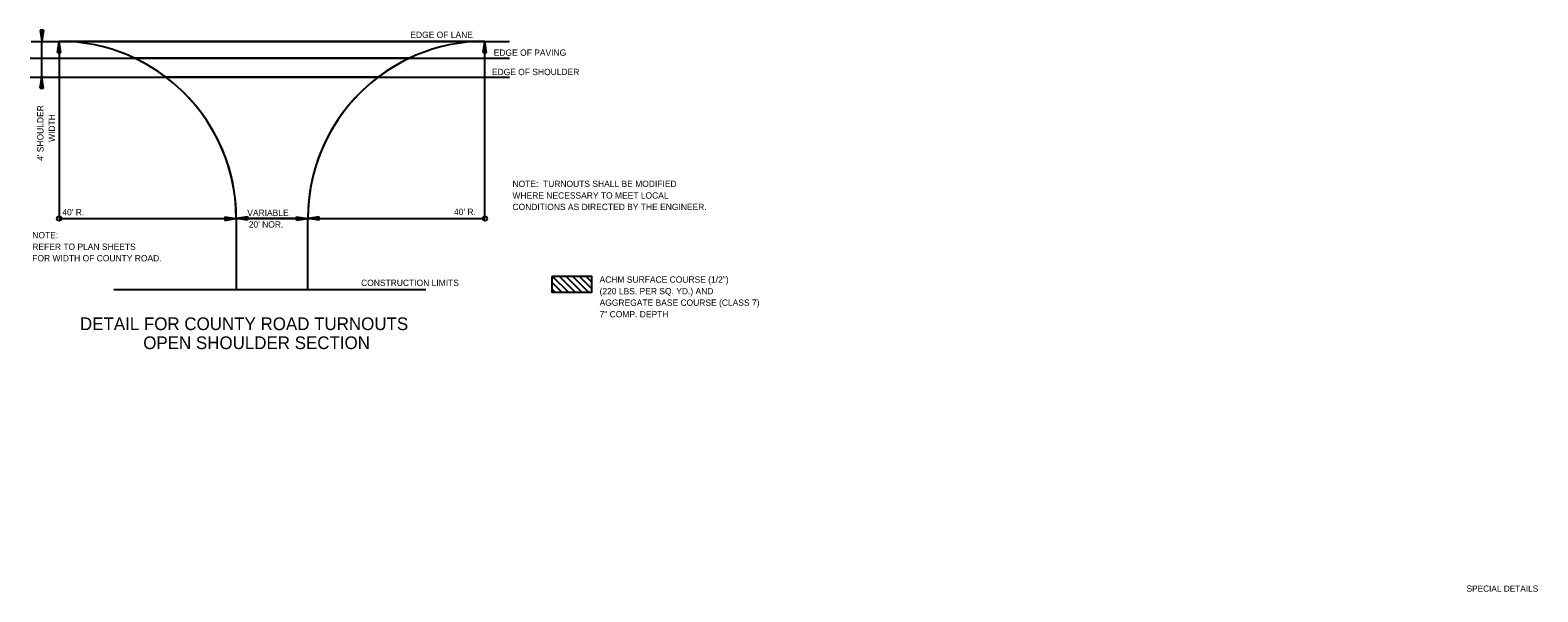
# Model space of a CAD drawing. Extents: x 836 to 5683, y -463 to 1545.
# Drawn here: x 2060 to 3490, y 1013 to 1545 of the extents above; entities that cross this region are included whole.
import ezdxf

# ---------------------------------------------------------------- set-up
doc = ezdxf.new("R2010")
doc.units = 0
doc.layers.add('Default', color=7, linetype='Continuous')
doc.layers.add('R_Border Prem', color=7, linetype='Continuous')

msp = doc.modelspace()

# ---------------------------------------------------------------- linework, layer by layer
at = {"layer": 'Default'}
for p, q in [((2069.7, 1544.8), (2071.2, 1534.2)), ((2072.8, 1544.8), (2069.7, 1544.8)), ((2069.9, 1544.8), (2071.2, 1536)), ((2070.2, 1544.8), (2071.2, 1537.8)), ((2070.5, 1544.8), (2071.2, 1539.5)), ((2070.7, 1544.8), (2071.2, 1541.4)), ((2071, 1544.8), (2071.2, 1543.1)), ((2072.8, 1544.8), (2071.2, 1534.2)), ((2071.8, 1544.8), (2071.2, 1541.4)), ((2072.3, 1544.8), (2071.2, 1537.8)), ((2072.6, 1544.8), (2071.2, 1536)), ((2072, 1544.8), (2071.2, 1539.5)), ((2071.5, 1544.8), (2071.2, 1543.1)), ((2061.2, 1534.2), (2514.7, 1534.2)), ((2071.2, 1500.3), (2071.2, 1534.2)), ((2086.2, 1523.6), (2087.8, 1534.2)), ((2086.5, 1523.6), (2087.8, 1532.4)), ((2086.7, 1523.6), (2087.8, 1530.6)), ((2089.4, 1523.6), (2087.8, 1534.2)), ((2087.8, 1534.2), (2087.8, 1366.3)), ((2491.4, 1534.2), (2087.8, 1534.2)), ((2089.1, 1523.6), (2087.8, 1532.4)), ((2088.9, 1523.6), (2087.8, 1530.6)), ((2251.1, 1533.8), (2251.3, 1534.3)), ((2251.3, 1534.2), (2251.1, 1533.8)), ((2251.1, 1533.8), (2251.3, 1534)), ((2489.8, 1523.6), (2491.4, 1534.2)), ((2490.1, 1523.6), (2491.4, 1532.4)), ((2490.3, 1523.6), (2491.4, 1530.6)), ((2493, 1523.6), (2491.4, 1534.2)), ((2491.4, 1366.3), (2491.4, 1534.2)), ((2492.7, 1523.6), (2491.4, 1532.4)), ((2492.4, 1523.6), (2491.4, 1530.6)), ((2060.3, 1518.3), (2514.7, 1518.3)), ((2086.2, 1523.6), (2089.4, 1523.6)), ((2087, 1523.6), (2087.8, 1528.8)), ((2087.3, 1523.6), (2087.8, 1527.1)), ((2087.5, 1523.6), (2087.8, 1525.3)), ((2088.6, 1523.6), (2087.8, 1528.8)), ((2088.3, 1523.6), (2087.8, 1527.1)), ((2088.1, 1523.6), (2087.8, 1525.3)), ((2420.1, 1518.3), (2159.1, 1518.3)), ((2489.8, 1523.6), (2493, 1523.6)), ((2490.6, 1523.6), (2491.4, 1528.8)), ((2490.9, 1523.6), (2491.4, 1527)), ((2491.1, 1523.6), (2491.4, 1525.3)), ((2492.2, 1523.6), (2491.4, 1528.8)), ((2491.9, 1523.6), (2491.4, 1527)), ((2491.7, 1523.6), (2491.4, 1525.3)), ((2060.3, 1500.3), (2514.7, 1500.3)), ((2069.7, 1489.7), (2071.2, 1500.3)), ((2069.7, 1489.7), (2072.8, 1489.7)), ((2069.9, 1489.7), (2071.2, 1498.5)), ((2070.2, 1489.7), (2071.2, 1496.7)), ((2070.5, 1489.7), (2071.2, 1494.9)), ((2070.8, 1489.7), (2071.2, 1493.1)), ((2071, 1489.7), (2071.2, 1491.4)), ((2072.8, 1489.7), (2071.2, 1500.3)), ((2072.6, 1489.7), (2071.2, 1498.5)), ((2072.3, 1489.7), (2071.2, 1496.7)), ((2072, 1489.7), (2071.2, 1494.9)), ((2071.8, 1489.7), (2071.2, 1493.1)), ((2071.5, 1489.7), (2071.2, 1491.4)), ((2390.2, 1500.3), (2188.9, 1500.3)), ((2087.8, 1366.3), (2255.7, 1366.3)), ((2244.7, 1367.8), (2255.3, 1366.2)), ((2244.7, 1367.8), (2244.7, 1364.6)), ((2244.7, 1367.6), (2253.5, 1366.2)), ((2244.7, 1367.3), (2251.7, 1366.2)), ((2244.7, 1367), (2249.9, 1366.2)), ((2244.7, 1366.7), (2248.1, 1366.2)), ((2244.7, 1366.5), (2246.4, 1366.2)), ((2244.7, 1364.6), (2255.3, 1366.2)), ((2244.7, 1365.7), (2248.1, 1366.2)), ((2244.7, 1365.2), (2251.7, 1366.2)), ((2244.7, 1364.9), (2253.5, 1366.2)), ((2244.7, 1365.4), (2249.9, 1366.2)), ((2244.7, 1366), (2246.4, 1366.2)), ((2255.7, 1366.3), (2255.7, 1299)), ((2255.7, 1366.3), (2323.5, 1366.3)), ((2255.7, 1366.3), (2323.5, 1366.3)), ((2255.7, 1366.3), (2256.9, 1366.3)), ((2256.9, 1366.3), (2255.7, 1366.3)), ((2255.7, 1366.3), (2255.7, 1299)), ((2266.4, 1368), (2255.8, 1366.5)), ((2255.8, 1366.5), (2266.4, 1368)), ((2266.4, 1364.9), (2255.8, 1366.5)), ((2256.9, 1366.3), (2255.8, 1366.5)), ((2266.4, 1364.9), (2256.9, 1366.3)), ((2266.4, 1367.8), (2257.6, 1366.5)), ((2266.4, 1365.1), (2257.6, 1366.5)), ((2266.4, 1367.5), (2259.4, 1366.5)), ((2266.4, 1365.4), (2259.4, 1366.5)), ((2266.4, 1367.3), (2261.2, 1366.5)), ((2266.4, 1365.7), (2261.2, 1366.5)), ((2266.4, 1367), (2263, 1366.5)), ((2266.4, 1365.9), (2263, 1366.5)), ((2266.4, 1366.7), (2264.8, 1366.5)), ((2266.4, 1366.2), (2264.8, 1366.5)), ((2266.4, 1368.1), (2266.4, 1366.3)), ((2266.4, 1364.9), (2266.4, 1368)), ((2266.4, 1366.3), (2312.9, 1366.3)), ((2312.9, 1366.3), (2266.4, 1366.3)), ((2266.4, 1366.3), (2266.4, 1364.9)), ((2312.9, 1367.9), (2323.5, 1366.3)), ((2312.9, 1367.9), (2312.9, 1364.7)), ((2312.9, 1366.3), (2312.9, 1367.9)), ((2312.9, 1367.9), (2323.5, 1366.3)), ((2312.9, 1367.6), (2321.7, 1366.3)), ((2312.9, 1367.3), (2319.9, 1366.3)), ((2312.9, 1367), (2318.1, 1366.3)), ((2312.9, 1366.8), (2316.3, 1366.3)), ((2312.9, 1366.5), (2314.6, 1366.3)), ((2312.9, 1364.7), (2323.5, 1366.3)), ((2312.9, 1365.8), (2316.3, 1366.3)), ((2312.9, 1365.2), (2319.9, 1366.3)), ((2312.9, 1364.9), (2321.7, 1366.3)), ((2312.9, 1365.5), (2318.1, 1366.3)), ((2312.9, 1366), (2314.6, 1366.3)), ((2323.5, 1366.3), (2312.9, 1364.7)), ((2312.9, 1364.7), (2312.9, 1366.3)), ((2323.5, 1299), (2323.5, 1366.3)), ((2323.5, 1366.3), (2491.4, 1366.3)), ((2323.5, 1299), (2323.5, 1366.3)), ((2334.2, 1368), (2323.7, 1366.5)), ((2334.2, 1364.9), (2323.7, 1366.5)), ((2334.2, 1367.8), (2325.4, 1366.5)), ((2334.2, 1365.1), (2325.4, 1366.5)), ((2334.2, 1367.5), (2327.2, 1366.5)), ((2334.2, 1365.4), (2327.2, 1366.5)), ((2334.2, 1367.3), (2329, 1366.5)), ((2334.2, 1365.7), (2329, 1366.5)), ((2334.2, 1367), (2330.8, 1366.5)), ((2334.2, 1365.9), (2330.8, 1366.5)), ((2334.2, 1366.7), (2332.5, 1366.5)), ((2334.2, 1366.2), (2332.5, 1366.5)), ((2334.2, 1364.9), (2334.2, 1368)), ((2139.7, 1299), (2435.3, 1299)), ((2255.7, 1299), (2323.5, 1299))]:
    msp.add_line(p, q, dxfattribs=at)
for points in [[(2188.9, 1500.3), (2390.2, 1500.3), (2390.2, 1500.3)], [(2554.8, 1306.1), (2564.2, 1296.6)], [(2555.6, 1311.5), (2570.6, 1296.6)], [(2562, 1311.5), (2576.9, 1296.6)], [(2568.3, 1311.5), (2583.2, 1296.6)], [(2574.6, 1311.5), (2589.6, 1296.6)], [(2581, 1311.5), (2592.9, 1299.6)], [(2587.3, 1311.5), (2592.9, 1306)], [(2554.8, 1299.7), (2557.9, 1296.6)]]:
    msp.add_lwpolyline(points, dxfattribs=at)
msp.add_lwpolyline([(2554.8, 1311.5), (2554.8, 1296.6), (2592.9, 1296.6), (2592.9, 1311.5)], close=True, dxfattribs=at)
for centre in [(2087.8, 1366.3), (2491.4, 1366.3)]:
    msp.add_circle(centre, 2.12, dxfattribs=at)
for centre, start, end in [((2087.8, 1366.3), 0, 90), ((2087.8, 1366.3), 0, 90), ((2491.4, 1366.3), 90, 180), ((2491.4, 1366.3), 90, 180), ((2087.8, 1366.3), 52.9538, 64.862), ((2491.4, 1366.3), 115.138, 127.0462), ((2087.8, 1366.3), 0.0007, 52.9538), ((2491.4, 1366.3), 127.0464, 180)]:
    msp.add_arc(centre, 167.9, start, end, dxfattribs=at)

# ---------------------------------------------------------------- texts
for s, height, p in [('EDGE OF LANE', 6, (2420.7, 1537.4)), ('EDGE OF PAVING', 6, (2499.8, 1520.5)), ('EDGE OF SHOULDER', 6, (2498, 1502.2)), ('NOTE:  TURNOUTS SHALL BE MODIFIED ', 6, (2517.5, 1396.2)), ('WHERE NECESSARY TO MEET LOCAL ', 6, (2517.5, 1385.2)), ("40' R.", 6, (2090.8, 1369.3)), ('VARIABLE', 6, (2266.1, 1368.7)), ("40' R.", 6, (2462.1, 1369.6)), ('CONDITIONS AS DIRECTED BY THE ENGINEER.', 6, (2517.5, 1374.3)), ("20' NOR.", 6, (2267.5, 1357.7)), ('NOTE:', 6, (2062.3, 1347.6)), ('REFER TO PLAN SHEETS', 6, (2062.3, 1336.6)), ('FOR WIDTH OF COUNTY ROAD.', 6, (2062.3, 1325.7)), ('CONSTRUCTION LIMITS', 6, (2374, 1302.4)), ('ACHM SURFACE COURSE (1/2") ', 6, (2600.1, 1305.5)), ('(220 LBS. PER SQ. YD.) AND ', 6, (2600.1, 1294.5)), ('AGGREGATE BASE COURSE (CLASS 7)', 6, (2600.1, 1283.6)), ('DETAIL FOR COUNTY ROAD TURNOUTS', 12, (2107.5, 1260.6)), ('7" COMP. DEPTH', 6, (2600.1, 1272.6)), ('OPEN SHOULDER SECTION', 12, (2167.5, 1242.6))]:
    msp.add_text(s, height=height, dxfattribs=at).set_placement(p)
for s, p in [("4' SHOULDER", (2072.9, 1420.9)), ('WIDTH', (2083.8, 1438.9))]:
    msp.add_text(s, height=6, rotation=90, dxfattribs=at).set_placement(p)
at = {"layer": 'R_Border Prem'}
msp.add_text('SPECIAL DETAILS', height=5.862, dxfattribs=at).set_placement((3422, 1012.7))

doc.saveas('drawing.dxf')
